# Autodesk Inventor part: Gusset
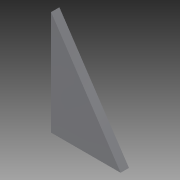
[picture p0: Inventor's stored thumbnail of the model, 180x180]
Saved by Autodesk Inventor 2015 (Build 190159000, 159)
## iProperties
Created: 2007-02
Part Number: Gusset
Material: Aluminum-6061
Document SubType Name: Modeling
Designer: Autodesk, Inc.
Mass: 3.9968 g
Surface Area: 13.0086 cm^2
Volume: 1.47484 cm^3
Density: 2.71 g/cm^3
Appearance: Aluminum - Flat
Author: Autodesk, Inc.
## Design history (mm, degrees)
sketch "Sketch1"
  geometry: L1 (243.925, 21.051)-(218.525, 21.051); L2 (218.525, 21.051)-(218.525, 59.151); L3 (218.525, 59.151)-(243.925, 21.051)
  constraints: 6 end point, 1 horizontal, 1 perpendicular
  dimensions: "d0" = 25.4 distance of L1.start L1.end; "d1" = 38.1 distance of L1.end L2.end
extrude "Extrusion1" new body sketch "Sketch1" distance "d2" = 3.048; taper "d3" = 0 deg
body "Solid1"
